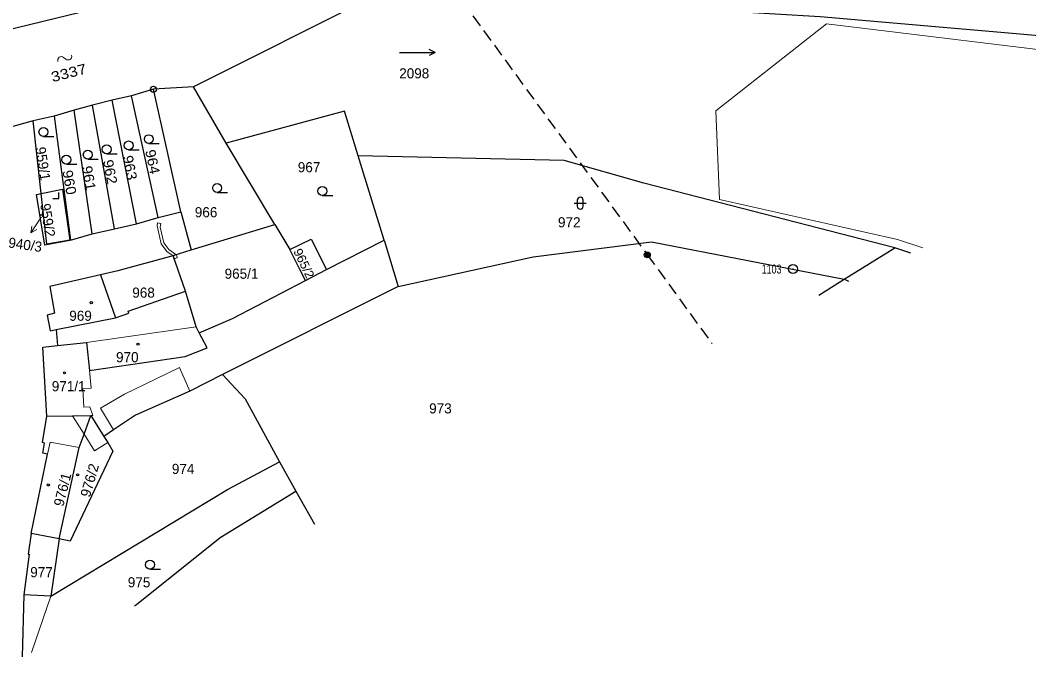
# Model space of a CAD drawing. Extents: x -546984 to -546090, y -1194931 to -1194069.
# Drawn here: x -546758.1 to -546588.4, y -1194875.4 to -1194768.4 of the extents above; entities that cross this region are included whole.
import ezdxf
from ezdxf.enums import TextEntityAlignment as Align

# ---------------------------------------------------------------- set-up
doc = ezdxf.new("R2010")
doc.units = 0
doc.header["$LTSCALE"] = 0.68
doc.linetypes.add('MEDIUM_DASHED', pattern=[4.5, 3, -1.5])
for name, color, linetype, lineweight in [('1', 7, 'Continuous', 25), ('13', 7, 'Continuous', 13), ('3', 7, 'Continuous', 25), ('4', 7, 'Continuous', 13), ('5', 7, 'Continuous', 25), ('6', 7, 'Continuous', 25), ('7', 7, 'Continuous', 13), ('8', 7, 'Continuous', 25)]:
    doc.layers.add(name, color=color, linetype=linetype, lineweight=lineweight)
doc.layers.add('2', color=7, linetype='Continuous')

msp = doc.modelspace()

# ---------------------------------------------------------------- linework, layer by layer
at = {"layer": '1'}
for p, q in [((-546682.73, -1194756.38), (-546728.98, -1194779.57)), ((-546623.54, -1194767.75), (-546586.67, -1194770.93)), ((-546728.98, -1194779.57), (-546735.71, -1194779.97)), ((-546723.45, -1194789.02), (-546728.98, -1194779.57)), ((-546739.38, -1194781.09), (-546742.66, -1194781.82)), ((-546735.71, -1194779.97), (-546739.38, -1194781.09)), ((-546745.97, -1194782.67), (-546749.06, -1194783.47)), ((-546742.66, -1194781.82), (-546745.97, -1194782.67)), ((-546752.4, -1194784.47), (-546755.97, -1194785.28)), ((-546749.06, -1194783.47), (-546752.4, -1194784.47)), ((-546755.97, -1194785.28), (-546762.54, -1194787.1)), ((-546715.3, -1194802.69), (-546723.45, -1194789.02)), ((-546696.9, -1194805.37), (-546701.27, -1194791.19)), ((-546731.11, -1194800.61), (-546729.37, -1194807)), ((-546729.37, -1194807), (-546715.3, -1194802.69)), ((-546715.3, -1194802.69), (-546712.78, -1194806.92)), ((-546749.69, -1194805.34), (-546749.81, -1194805.36)), ((-546706.57, -1194810.27), (-546696.9, -1194805.37)), ((-546608.245, -1194807.545), (-546610.97, -1194806.64)), ((-546710.14, -1194812.13), (-546706.57, -1194810.27)), ((-546623.739, -1194814.578), (-546619.48, -1194811.93)), ((-546618.699, -1194812.29), (-546619.48, -1194811.93)), ((-546752.08, -1194820.39), (-546742.08, -1194818.42)), ((-546751.58, -1194855.58), (-546756.31, -1194854.68)), ((-546751.58, -1194855.58), (-546752.98, -1194865.21)), ((-546738.895, -1194866.852), (-546738.58, -1194866.63)), ((-546738.537, -1194866.689), (-546738.58, -1194866.63))]:
    msp.add_line(p, q, dxfattribs=at)
for points in [[(-546832.61, -1194792.18), (-546832.81, -1194779.81), (-546791.87, -1194777.31), (-546762.86, -1194770.59), (-546745.98, -1194766.47), (-546719.75, -1194757.14), (-546687.4, -1194741.31)], [(-546682.73, -1194756.38), (-546658.62, -1194766.93), (-546638.65, -1194766.81), (-546623.54, -1194767.75), (-546586.67, -1194770.93), (-546567.2, -1194774.9)], [(-546738.57, -1194802.6), (-546734.94, -1194801.56), (-546739.38, -1194781.09)], [(-546734.94, -1194801.56), (-546731.11, -1194800.61), (-546735.71, -1194779.97)], [(-546746, -1194804.26), (-546742.28, -1194803.43), (-546745.97, -1194782.67)], [(-546742.28, -1194803.43), (-546738.57, -1194802.6), (-546742.66, -1194781.82)], [(-546752.4, -1194784.47), (-546749.69, -1194805.34), (-546746, -1194804.26), (-546749.06, -1194783.47)], [(-546701.27, -1194791.19), (-546703.58, -1194783.68), (-546723.45, -1194789.02)], [(-546749.81, -1194805.36), (-546749.8, -1194805.43), (-546754.01, -1194806.18), (-546755.37, -1194797.65), (-546754.62, -1194797.5), (-546755.97, -1194785.28)], [(-546610.97, -1194806.64), (-546653.17, -1194795.75), (-546666.57, -1194791.96), (-546701.27, -1194791.19)], [(-546754.62, -1194797.5), (-546751.02, -1194796.76), (-546749.81, -1194805.36)], [(-546749.81, -1194805.36), (-546753.68, -1194806.05), (-546754.62, -1194797.5)], [(-546712.78, -1194806.92), (-546709.18, -1194805.16), (-546706.57, -1194810.27)], [(-546696.9, -1194805.37), (-546694.51, -1194813.13), (-546724.12, -1194827.96)], [(-546710.14, -1194812.13), (-546711.15, -1194810.19), (-546712.78, -1194806.92)], [(-546694.51, -1194813.13), (-546671.79, -1194808.17), (-546651.89, -1194805.61), (-546619.48, -1194811.93), (-546610.97, -1194806.64)], [(-546732.38, -1194808.01), (-546732.82, -1194808.12), (-546741.71, -1194810.48), (-546744.6, -1194811.16), (-546742.08, -1194818.42)], [(-546742.08, -1194818.42), (-546739.86, -1194817.65), (-546739.95, -1194817.3), (-546730.34, -1194813.95), (-546732.38, -1194808.01)], [(-546732.38, -1194808.01), (-546732.25, -1194807.88), (-546729.37, -1194807)], [(-546744.6, -1194811.16), (-546753.13, -1194813.14), (-546752.34, -1194817.64), (-546753.57, -1194817.95), (-546753.12, -1194820.59), (-546752.08, -1194820.39), (-546751.86, -1194823.09)], [(-546728.01, -1194820.91), (-546722.41, -1194818.52), (-546710.14, -1194812.13)], [(-546728.01, -1194820.91), (-546728.53, -1194819.93), (-546730.34, -1194813.95)], [(-546751.86, -1194823.09), (-546746.99, -1194822.58), (-546746.47, -1194827.28), (-546730.38, -1194824.9), (-546726.66, -1194823.47), (-546728.01, -1194820.91)], [(-546753.64, -1194834.98), (-546754.34, -1194823.36), (-546751.86, -1194823.09)], [(-546724.12, -1194827.96), (-546729.59, -1194830.77), (-546738.73, -1194834.8), (-546742.44, -1194837.26), (-546744.07, -1194838.35)], [(-546724.12, -1194827.96), (-546720.28, -1194832.06), (-546714.48, -1194842.63)], [(-546756.31, -1194854.68), (-546753.53, -1194841.32), (-546754.34, -1194841.17), (-546754.02, -1194839.47), (-546754.37, -1194839.39), (-546753.64, -1194834.98)], [(-546753.64, -1194834.98), (-546749.32, -1194834.89), (-546746.25, -1194834.83), (-546744.07, -1194838.35)], [(-546751.58, -1194855.58), (-546748.19, -1194840.2), (-546747.39, -1194837.98), (-546746.25, -1194834.83)], [(-546744.07, -1194838.35), (-546743.41, -1194839.4), (-546742.52, -1194840.85), (-546749.74, -1194855.99), (-546751.58, -1194855.58)], [(-546752.98, -1194865.21), (-546723.24, -1194847.31), (-546714.48, -1194842.63)], [(-546714.48, -1194842.63), (-546711.73, -1194847.59), (-546708.635, -1194853.115)], [(-546738.58, -1194866.63), (-546724.51, -1194855.37), (-546711.73, -1194847.59)], [(-546756.31, -1194854.68), (-546756.78, -1194858.14), (-546756.62, -1194858.16), (-546757.51, -1194865.02)], [(-546752.98, -1194865.21), (-546757.51, -1194865.02), (-546757.789, -1194875.428)]]:
    msp.add_lwpolyline(points, dxfattribs=at)
at = {"layer": '13'}
for points in [[(-546735.05, -1194802.46), (-546735.11, -1194802.96), (-546734.41, -1194805.98), (-546733.48, -1194807.28), (-546732.38, -1194808.01), (-546732.25, -1194807.88), (-546731.92, -1194807.78), (-546733.14, -1194806.92), (-546733.95, -1194805.8), (-546734.59, -1194803.15), (-546734.47, -1194802.54)], [(-546731.67, -1194808.26), (-546731.92, -1194807.78), (-546732.25, -1194807.88), (-546732.38, -1194808.01), (-546732.12, -1194808.47)]]:
    msp.add_lwpolyline(points, close=True, dxfattribs=at)
at = {"layer": '3'}
for p, q in [((-546688.32, -1194773.778), (-546689.297, -1194774.279)), ((-546754.223, -1194787.9), (-546752.473, -1194787.9)), ((-546736.493, -1194789.11), (-546734.743, -1194789.11)), ((-546743.593, -1194790.83), (-546741.843, -1194790.83)), ((-546739.883, -1194790.17), (-546738.133, -1194790.17)), ((-546750.363, -1194792.57), (-546748.613, -1194792.57)), ((-546746.763, -1194791.72), (-546745.013, -1194791.72)), ((-546724.993, -1194797.33), (-546723.243, -1194797.33)), ((-546707.293, -1194797.84), (-546705.543, -1194797.84)), ((-546664.891, -1194799.141), (-546662.889, -1194799.141)), ((-546664.391, -1194798.641), (-546664.391, -1194799.642)), ((-546663.389, -1194799.642), (-546663.389, -1194798.641)), ((-546736.293, -1194860.69), (-546734.543, -1194860.69))]:
    msp.add_line(p, q, dxfattribs=at)
for points in [[(-546694.32, -1194773.778), (-546688.32, -1194773.778), (-546689.297, -1194773.276)], [(-546752.641, -1194798.36), (-546751.64, -1194798.36), (-546751.64, -1194797.36)], [(-546754.971, -1194801.09), (-546754.3, -1194801.09), (-546754.3, -1194800.42)]]:
    msp.add_lwpolyline(points, dxfattribs=at)
for centre in [(-546754.2229, -1194787.1498), (-546736.4929, -1194788.3598), (-546743.5929, -1194790.0798), (-546739.8829, -1194789.4198), (-546750.3629, -1194791.8198), (-546746.7629, -1194790.9698), (-546724.9929, -1194796.5798), (-546707.2929, -1194797.0898), (-546736.2929, -1194859.9398)]:
    msp.add_circle(centre, 0.75, dxfattribs=at)
for centre, start, end in [((-546663.89, -1194798.6409), 0, 180), ((-546663.89, -1194799.6409), 180, 359.98789)]:
    msp.add_arc(centre, 0.5, start, end, dxfattribs=at)
at = {"layer": '4'}
for p, q in [((-546746.99, -1194822.58), (-546728.53, -1194819.93)), ((-546731.33, -1194826.78), (-546729.59, -1194830.77)), ((-546746.25, -1194834.83), (-546745.94, -1194834.82)), ((-546745.64, -1194840.78), (-546743.41, -1194839.4)), ((-546756.243, -1194874.726), (-546752.98, -1194865.21))]:
    msp.add_line(p, q, dxfattribs=at)
for points in [[(-546606.239, -1194806.634), (-546610.5, -1194805.22), (-546640.44, -1194798.5), (-546641.05, -1194783.61), (-546622.46, -1194768.95)], [(-546622.46, -1194768.95), (-546576.31, -1194774.57), (-546581.06, -1194787.16), (-546580.633, -1194795.011)], [(-546746.47, -1194827.28), (-546746.18, -1194830.24), (-546747.6, -1194830.36), (-546747.42, -1194833.43), (-546746.4, -1194833.39), (-546745.94, -1194834.82)], [(-546740.61, -1194831.25), (-546735.25, -1194828.67), (-546731.33, -1194826.78)], [(-546742.44, -1194837.26), (-546744.61, -1194833.58), (-546740.61, -1194831.25)], [(-546749.32, -1194834.89), (-546747.39, -1194837.98), (-546745.64, -1194840.78)], [(-546753.53, -1194841.32), (-546753.08, -1194839.31), (-546748.19, -1194840.2)]]:
    msp.add_lwpolyline(points, dxfattribs=at)
at = {"layer": '5', "lineweight": 13}
msp.add_line((-546750.855, -1194774.627), (-546750.437, -1194774.902), dxfattribs=at)
at = {"layer": '5'}
for centre in [(-546746.1668, -1194815.8592), (-546738.3068, -1194822.8292), (-546750.6868, -1194827.6592), (-546748.4668, -1194844.8192), (-546753.4068, -1194846.5192)]:
    msp.add_circle(centre, 0.175, dxfattribs=at)
at = {"layer": '5', "lineweight": 13}
for centre, start, end in [((-546751.2387, -1194775.0724), 49.18469, 201.1122), ((-546750.0523, -1194774.457), 229.18468, 21.1122)]:
    msp.add_arc(centre, 0.5876, start, end, dxfattribs=at)
at = {"layer": '6', "linetype": 'MEDIUM_DASHED'}
for p, q in [((-546732.48, -1194698.43), (-546652.61, -1194807.81)), ((-546652.61, -1194807.81), (-546641.72, -1194822.74))]:
    msp.add_line(p, q, dxfattribs=at)
at = {"layer": '6'}
for radius in [0.5, 0.4, 0.3, 0.2, 0.1]:
    msp.add_circle((-546652.6134, -1194807.8099), radius, dxfattribs=at)
at = {"layer": '7'}
msp.add_line((-546756.338, -1194804.108), (-546755.363, -1194803.558), dxfattribs=at)
msp.add_lwpolyline([(-546754.57, -1194801.5), (-546754.66, -1194801.62), (-546756.338, -1194804.108), (-546756.193, -1194802.998)], dxfattribs=at)
at = {"layer": '8'}
for centre, radius in [((-546735.71, -1194779.9699), 0.5), ((-546735.71, -1194779.9699), 0.0303), ((-546628.09, -1194810.2098), 0.75), ((-546628.09, -1194810.2098), 0.03)]:
    msp.add_circle(centre, radius, dxfattribs=at)

# ---------------------------------------------------------------- texts
at = {"layer": '2', "width": 1.2}
msp.add_text('3337', height=1.7, rotation=14.378, dxfattribs=at).set_placement((-546752.684, -1194778.783))
at = {"layer": '2'}
for s, p in [('2098', (-546691.826, -1194778.138)), ('972', (-546665.739, -1194803.19)), ('965/1', (-546720.89, -1194811.84)), ('968', (-546737.379, -1194815.02)), ('969', (-546747.979, -1194818.91)), ('970', (-546740.109, -1194825.88)), ('973', (-546687.419, -1194834.49)), ('974', (-546730.719, -1194844.67)), ('977', (-546754.549, -1194862.04)), ('975', (-546738.129, -1194863.74))]:
    msp.add_text(s, height=1.7, dxfattribs=at).set_placement(p, align=Align.CENTER)
for s, rotation, p in [('959/1', 279, (-546755.579, -1194789.812)), ('959/2', 279, (-546754.779, -1194799.322)), ('976/2', 74, (-546746.412, -1194848.704)), ('976/1', 76, (-546750.885, -1194850.255))]:
    msp.add_text(s, height=1.7, rotation=rotation, dxfattribs=at).set_placement(p)
for s, height, rotation, width, p in [('963', 1.7, 281, 1.1, (-546740.4931, -1194793.3198)), ('964', 1.7, 282, 1.1, (-546736.6864, -1194792.3443)), ('961', 1.7, 280, 1.1, (-546747.3998, -1194795.0549)), ('962', 1.7, 281, 1.1, (-546743.8231, -1194794.0398)), ('960', 1.7, 280, 1.1, (-546750.6798, -1194795.7749)), ('965/2', 1.502, 296, 1.05, (-546711.0576, -1194809.5883))]:
    msp.add_text(s, height=height, rotation=rotation, dxfattribs=dict(at, width=width)).set_placement(p, align=Align.CENTER)
for s, p in [('967', (-546711.42, -1194793.93)), ('966', (-546728.75, -1194801.5)), ('971/1', (-546752.82, -1194830.76))]:
    msp.add_text(s, height=1.7, dxfattribs=at).set_placement(p)
msp.add_text('940/3', height=1.7, rotation=352, dxfattribs=at).set_placement((-546754.5866, -1194807.3571), align=Align.RIGHT)
at = {"layer": '8', "width": 0.75}
msp.add_text('1103', height=1.5, dxfattribs=at).set_placement((-546630.02, -1194810.96), align=Align.RIGHT)

doc.saveas('drawing.dxf')
